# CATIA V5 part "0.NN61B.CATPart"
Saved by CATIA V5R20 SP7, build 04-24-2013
Part number: 0.NN61B
Material "Nessuno"
Bounding box of the stored display mesh (mm): x 0 to 150.807, y -131.181 to 0, z -91.151 to 75.737
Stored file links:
  C:\Users\designer2\Desktop\Ottobre 2022\25-10-2022\04\Yori Evo 48V\0.NN61B.CATPart
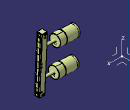
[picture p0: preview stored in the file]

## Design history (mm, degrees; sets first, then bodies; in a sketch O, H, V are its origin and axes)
AxisSystem1: origin (0, 0, 0), X (1, 0, 0), Y (0, 1, 0), Z (0, 0, 1)
Set1
  DatumSurface1
Body1 (main body), material "Nessuno"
